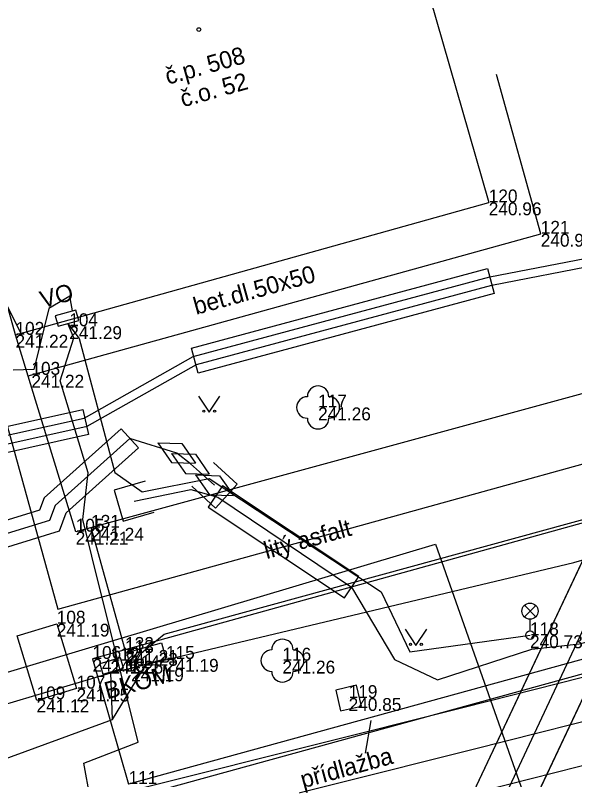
# Model space of a CAD drawing. Extents: x -599432 to -598680, y -1159407 to -1158632.
# Drawn here: x -599009.82 to -598996.8, y -1158877.11 to -1158859.33 of the extents above; entities that cross this region are included whole.
import ezdxf

# ---------------------------------------------------------------- set-up
doc = ezdxf.new("R2010")
doc.units = 0
for name, color, linetype in [('0004 VY - Body podrobné', 7, 'Continuous'), ('0005 VY - Body podrobné - čísla', 7, 'Continuous'), ('0006 VY - Body podrobné - výšky', 7, 'Continuous'), ('0007 ZA - Budova - zděná', 7, 'Continuous'), ('0010 ZA - Budova - označení', 7, 'Continuous'), ('0027 ZA - Silnice_cesta zpevněná', 7, 'Continuous'), ('0030 ZA - Chodník', 7, 'Continuous'), ('0031 ZA - Ostatní rozhraní', 7, 'Continuous'), ('0032 TE - Popis povrchu', 7, 'Continuous'), ('0034 ZA - Kultury - značky', 7, 'Continuous'), ('0035 ZA - Strom - značka', 7, 'Continuous'), ('0049 TE - Orientační _ popisná čísla', 7, 'Continuous'), ('0057 ZA - Doprava - BKOM buňky', 7, 'Continuous'), ('0058 TE - Doprava - BKOM popis', 7, 'Continuous'), ('0105 ZA - TSB - VO - buňky', 7, 'Continuous'), ('0106 TE - TSB - VO - popis', 7, 'Continuous'), ('0116 PV - budova převzatá z mapy', 7, 'Continuous'), ('0203 PV - BVK - kanalizace - dešťová přípojka', 7, 'Continuous'), ('0302 PV - RWE - NTL', 7, 'Continuous'), ('0308 PV - RWE - ochranné pásmo', 7, 'Continuous'), ('0352 PV - EON - NN', 7, 'Continuous'), ('0354 PV - EON - VN', 7, 'Continuous'), ('0367 PV - EON - VN chránička', 7, 'Continuous'), ('0407 PV - TSB - kabelové vedení přibližný zákres', 7, 'Continuous'), ('0455 PV - O2 - kabel nezaměřený', 7, 'Continuous'), ('0456 PV - O2 - sítě s NN', 7, 'Continuous'), ('0457 PV - O2 - kabelovod', 7, 'Continuous'), ('0551 PV - NETBOX - buňky', 7, 'Continuous'), ('0552 PV - NETBOX - vedení', 7, 'Continuous'), ('0552 PV - OT VUT', 7, 'Continuous'), ('0553 PV - NETBOX - chranička', 7, 'Continuous'), ('0652 PV - BKOM - kabely bez rozlišení', 7, 'Continuous'), ('0750 ZA - nerozlišené sítě - buňky', 7, 'Continuous')]:
    doc.layers.add(name, color=color, linetype=linetype)

msp = doc.modelspace()

# ---------------------------------------------------------------- linework, layer by layer
at = {"layer": '0004 VY - Body podrobné'}
for p, q in [((-598998.8, -1158863.68), (-598998.8, -1158863.68)), ((-598997.59, -1158864.41), (-598997.59, -1158864.41)), ((-599008.56, -1158866.56), (-599008.56, -1158866.56)), ((-599009.81, -1158866.76), (-599009.81, -1158866.76)), ((-599009.44, -1158867.69), (-599009.44, -1158867.69)), ((-599002.77, -1158868.45), (-599002.77, -1158868.45)), ((-599008.41, -1158871.34), (-599008.41, -1158871.34)), ((-599008.05, -1158871.25), (-599008.05, -1158871.25)), ((-599008.85, -1158873.48), (-599008.85, -1158873.48)), ((-598997.84, -1158873.75), (-598997.84, -1158873.75)), ((-599007.26, -1158874.09), (-599007.26, -1158874.09)), ((-599007.26, -1158874.16), (-599007.26, -1158874.16)), ((-599008.02, -1158874.3), (-599008.02, -1158874.3)), ((-599007.6, -1158874.34), (-599007.6, -1158874.34)), ((-599006.31, -1158874.3), (-599006.31, -1158874.3)), ((-599003.6, -1158874.34), (-599003.6, -1158874.34)), ((-599007.12, -1158874.52), (-599007.12, -1158874.52)), ((-599008.39, -1158874.99), (-599008.39, -1158874.99)), ((-599009.32, -1158875.24), (-599009.32, -1158875.24)), ((-599002.06, -1158875.21), (-599002.06, -1158875.21))]:
    msp.add_line(p, q, dxfattribs=at)
at = {"layer": '0007 ZA - Budova - zděná'}
msp.add_line((-599009.81, -1158866.76), (-598998.8, -1158863.68), dxfattribs=at)
at = {"layer": '0010 ZA - Budova - označení'}
msp.add_circle((-599005.545, -1158859.66), 0.0438, dxfattribs=at)
at = {"layer": '0027 ZA - Silnice_cesta zpevněná'}
msp.add_line((-598977.96, -1158869.18), (-599007.18, -1158877.21), dxfattribs=at)
at = {"layer": '0030 ZA - Chodník'}
for p, q in [((-598978.46, -1158863.18), (-599008.41, -1158871.34)), ((-598977.38, -1158865.8), (-599008.02, -1158874.3)), ((-599008.41, -1158871.34), (-599009.81, -1158866.76)), ((-599008.02, -1158874.3), (-599007.18, -1158877.21))]:
    msp.add_line(p, q, dxfattribs=at)
at = {"layer": '0031 ZA - Ostatní rozhraní'}
for p, q in [((-598997.59, -1158864.41), (-598998.616, -1158860.704)), ((-599009.519, -1158867.712), (-598997.59, -1158864.41)), ((-598977.872, -1158869.501), (-599007.092, -1158877.531)), ((-599007.26, -1158874.089), (-599008.052, -1158871.242))]:
    msp.add_line(p, q, dxfattribs=at)
at = {"layer": '0032 TE - Popis povrchu'}
msp.add_line((-599001.664, -1158876.492), (-599001.535, -1158875.734), dxfattribs=at)
at = {"layer": '0034 ZA - Kultury - značky'}
for points in [[(-599005.553, -1158868.187), (-599005.303, -1158868.562), (-599005.053, -1158868.187)], [(-599000.744, -1158873.61), (-599000.494, -1158873.985), (-599000.244, -1158873.61)]]:
    msp.add_lwpolyline(points, dxfattribs=at)
for centre in [(-599005.428, -1158868.537), (-599005.178, -1158868.537), (-599000.619, -1158873.96), (-599000.369, -1158873.96)]:
    msp.add_circle(centre, 0.025, dxfattribs=at)
at = {"layer": '0035 ZA - Strom - značka'}
for centre in [(-599002.77, -1158868.45), (-599003.6, -1158874.34)]:
    msp.add_circle(centre, 0.00025, dxfattribs=at)
for centre, start, end in [((-599002.77, -1158868.2), 0, 180), ((-599003.02, -1158868.45), 90, 270), ((-599002.52, -1158868.45), 270, 90), ((-599002.77, -1158868.7), 180, 360), ((-599003.6, -1158874.09), 0, 180), ((-599003.85, -1158874.34), 90, 270), ((-599003.35, -1158874.34), 270, 90), ((-599003.6, -1158874.59), 180, 360)]:
    msp.add_arc(centre, 0.25, start, end, dxfattribs=at)
at = {"layer": '0057 ZA - Doprava - BKOM buňky'}
for points in [[(-599006.31, -1158874.3), (-599007.12, -1158874.52), (-599007.221, -1158874.149), (-599006.411, -1158873.929)], [(-599007.781, -1158874.651), (-599007.3, -1158874.515), (-599007.368, -1158874.274), (-599007.849, -1158874.411)]]:
    msp.add_lwpolyline(points, close=True, dxfattribs=at)
at = {"layer": '0105 ZA - TSB - VO - buňky'}
for p, q in [((-598997.972, -1158873.319), (-598997.708, -1158873.055)), ((-598997.704, -1158873.318), (-598997.968, -1158873.053)), ((-598997.84, -1158873.65), (-598997.84, -1158873.375))]:
    msp.add_line(p, q, dxfattribs=at)
msp.add_lwpolyline([(-599008.819, -1158866.56), (-599008.336, -1158866.427), (-599008.403, -1158866.186), (-599008.885, -1158866.319)], close=True, dxfattribs=at)
for centre, radius in [((-598997.84, -1158873.188), 0.188), ((-598997.84, -1158873.75), 0.1)]:
    msp.add_circle(centre, radius, dxfattribs=at)
at = {"layer": '0116 PV - budova převzatá z mapy'}
for p, q in [((-599009.81, -1158866.76), (-599014.86, -1158848.7)), ((-599002.26, -1158851.67), (-598998.8, -1158863.68))]:
    msp.add_line(p, q, dxfattribs=at)
at = {"layer": '0203 PV - BVK - kanalizace - dešťová přípojka'}
msp.add_line((-599009.663, -1158866.757), (-599015.455, -1158855.336), dxfattribs=at)
msp.add_line((-599009.663, -1158866.757), (-599015.455, -1158855.336), dxfattribs=at)
at = {"layer": '0302 PV - RWE - NTL'}
msp.add_lwpolyline([(-599031.044, -1158884.383), (-598999.16, -1158876.4), (-598995.29, -1158875.42), (-598995.15, -1158875.39), (-598995.04, -1158875.36)], dxfattribs=at)
at = {"layer": '0308 PV - RWE - ochranné pásmo'}
msp.add_lwpolyline([(-599031.689, -1158883.514), (-599031.287, -1158883.413), (-598999.404, -1158875.43), (-598995.518, -1158874.446), (-598995.387, -1158874.418), (-598995.303, -1158874.395), (-598994.903, -1158874.286), (-598994.184, -1158874.697), (-598994.075, -1158875.097), (-598993.966, -1158875.497), (-598994.377, -1158876.216), (-598994.777, -1158876.325), (-598994.913, -1158876.362), (-598995.062, -1158876.394), (-598998.916, -1158877.37), (-599030.801, -1158885.353), (-599031.203, -1158885.454), (-599031.913, -1158885.028), (-599032.014, -1158884.626), (-599032.115, -1158884.224)], close=True, dxfattribs=at)
at = {"layer": '0352 PV - EON - NN'}
msp.add_lwpolyline([(-599021.682, -1158826.616), (-599018.026, -1158839.848), (-599017.168, -1158839.601), (-599017.124, -1158839.718), (-599017.057, -1158839.985), (-599017.919, -1158840.233), (-599016.234, -1158846.334), (-599013.125, -1158857.581), (-599012.296, -1158857.347), (-599012.256, -1158857.465), (-599012.187, -1158857.732), (-599013.017, -1158857.966), (-599008.822, -1158873.141), (-598963.861, -1158860.708)], dxfattribs=at)
at = {"layer": '0354 PV - EON - VN'}
for points in [[(-599068.426, -1158889.707), (-599062.435, -1158887.486), (-599057.559, -1158885.602), (-599053.514, -1158882.536), (-599048.468, -1158879.787), (-599040.575, -1158877.583), (-599039.069, -1158877.224), (-599035.277, -1158875.867), (-599021.599, -1158869.995), (-599019.639, -1158870.482), (-599018.747, -1158870.641), (-599017.491, -1158870.75), (-599015.995, -1158870.391), (-599015.549, -1158870.322), (-599008.216, -1158868.696), (-599005.678, -1158867.267), (-598998.773, -1158865.413), (-598996.328, -1158864.935), (-598994.319, -1158863.656), (-598989.416, -1158862.609), (-598988.122, -1158862.719), (-598986.867, -1158862.571), (-598978.725, -1158860.643), (-598971.459, -1158858.594)], [(-599068.354, -1158889.893), (-599062.365, -1158887.674), (-599057.461, -1158885.778), (-599053.406, -1158882.704), (-599048.392, -1158879.973), (-599040.525, -1158877.777), (-599039.011, -1158877.416), (-599035.203, -1158876.053), (-599021.581, -1158870.205), (-599019.681, -1158870.678), (-599018.773, -1158870.839), (-599017.509, -1158870.95), (-599015.965, -1158870.589), (-599015.511, -1158870.518), (-599008.144, -1158868.884), (-599005.602, -1158867.453), (-598998.727, -1158865.607), (-598996.252, -1158865.125), (-598994.241, -1158863.844), (-598989.404, -1158862.811), (-598988.118, -1158862.921), (-598986.833, -1158862.769), (-598978.675, -1158860.837), (-598971.401, -1158858.786)]]:
    msp.add_lwpolyline(points, dxfattribs=at)
at = {"layer": '0367 PV - EON - VN chránička'}
for p, q in [((-599005.718, -1158867.07), (-598998.828, -1158865.22)), ((-598998.828, -1158865.22), (-598998.672, -1158865.8)), ((-598998.672, -1158865.8), (-599005.562, -1158867.65)), ((-599005.562, -1158867.65), (-599005.718, -1158867.07)), ((-599015.595, -1158870.127), (-599008.245, -1158868.497)), ((-599008.245, -1158868.497), (-599008.115, -1158869.083)), ((-599008.115, -1158869.083), (-599015.465, -1158870.713))]:
    msp.add_line(p, q, dxfattribs=at)
at = {"layer": '0407 PV - TSB - kabelové vedení přibližný zákres'}
for p, q in [((-599008.545, -1158865.86), (-599009.036, -1158866.147)), ((-599008.484, -1158866.205), (-599008.545, -1158865.86)), ((-599009.036, -1158866.147), (-599009.384, -1158867.567)), ((-599008.452, -1158866.833), (-599008.593, -1158866.498)), ((-599008.593, -1158866.498), (-599008.325, -1158866.846)), ((-599008.771, -1158867.828), (-599008.452, -1158866.833)), ((-599008.325, -1158866.846), (-599007.502, -1158869.965)), ((-599009.384, -1158867.567), (-599009.862, -1158867.58)), ((-599008.121, -1158869.972), (-599008.771, -1158867.828)), ((-599008.243, -1158871.058), (-599008.121, -1158869.972)), ((-599007.502, -1158869.965), (-599006.864, -1158870.412)), ((-599006.864, -1158870.412), (-599005.307, -1158870.106)), ((-599005.307, -1158870.106), (-599002.705, -1158871.815)), ((-599008.031, -1158871.911), (-599008.243, -1158871.058)), ((-599002.705, -1158871.815), (-599001.301, -1158872.738)), ((-599006.96, -1158876.236), (-599008.031, -1158871.911)), ((-599001.301, -1158872.738), (-599000.638, -1158874.137)), ((-599000.638, -1158874.137), (-598997.84, -1158873.75)), ((-599008.223, -1158876.721), (-599006.96, -1158876.236)), ((-599006.22, -1158887.349), (-599008.223, -1158876.721))]:
    msp.add_line(p, q, dxfattribs=at)
at = {"layer": '0455 PV - O2 - kabel nezaměřený'}
for points in [[(-599011.61, -1158875.82), (-599007.59, -1158874.62), (-598996.82, -1158872.06), (-598955.03, -1158859.99), (-598940.58, -1158856.31), (-598931.77, -1158853.97)], [(-599004.95, -1158891.42), (-598992.56, -1158865)]]:
    msp.add_lwpolyline(points, dxfattribs=at)
at = {"layer": '0456 PV - O2 - sítě s NN'}
msp.add_lwpolyline([(-599004.95, -1158891.42), (-598992.56, -1158865)], dxfattribs=at)
at = {"layer": '0457 PV - O2 - kabelovod'}
for points in [[(-598994.01, -1158866.5), (-599005.01, -1158889.8)], [(-598992.66, -1158866.84), (-599003.78, -1158890.39)]]:
    msp.add_lwpolyline(points, dxfattribs=at)
at = {"layer": '0551 PV - NETBOX - buňky'}
for points in [[(-599006.499, -1158869.271), (-599005.943, -1158869.287)], [(-599006.499, -1158869.271), (-599006.177, -1158869.733)], [(-599005.943, -1158869.287), (-599005.621, -1158869.749)], [(-599006.179, -1158869.521), (-599005.623, -1158869.537)], [(-599006.179, -1158869.521), (-599005.857, -1158869.983)], [(-599005.623, -1158869.537), (-599005.301, -1158869.999)], [(-599006.177, -1158869.733), (-599005.621, -1158869.749)], [(-599005.71, -1158870.284), (-599005.156, -1158870.79), (-599004.65, -1158870.236), (-599005.204, -1158869.73)], [(-599005.857, -1158869.983), (-599005.301, -1158869.999)], [(-599005.619, -1158870.021), (-599005.063, -1158870.037)], [(-599005.619, -1158870.021), (-599005.297, -1158870.483)], [(-599005.063, -1158870.037), (-599004.741, -1158870.499)], [(-599006.796, -1158870.164), (-599007.515, -1158870.376), (-599007.304, -1158871.095), (-599006.584, -1158870.884)], [(-599005.297, -1158870.483), (-599004.741, -1158870.499)]]:
    msp.add_lwpolyline(points, dxfattribs=at)
at = {"layer": '0552 PV - NETBOX - vedení'}
for points in [[(-599007.05, -1158870.63), (-599005.73, -1158870.36), (-599005.1, -1158870.54), (-599001.99, -1158872.63), (-599000.99, -1158874.31), (-598999.99, -1158874.79), (-598997.8, -1158874.07), (-598996.7, -1158873.95), (-598994.84, -1158873.5), (-598993.019, -1158872.79), (-598991.84, -1158872.01), (-598990.22, -1158871.96), (-598984.72, -1158870.68), (-598978.84, -1158868.55), (-598975.909, -1158867.89)], [(-599006.06, -1158869.51), (-599006.06, -1158869.51), (-599007.15, -1158869.17), (-599007.15, -1158869.17), (-599008.89, -1158870.73), (-599009.02, -1158871.08), (-599010.62, -1158871.57), (-599015.34, -1158873.36), (-599021.01, -1158874.99), (-599029.72, -1158877.35), (-599032.35, -1158878.18), (-599038.52, -1158879.88), (-599044.56, -1158881.49), (-599050.4, -1158884.03), (-599052.74, -1158885.29), (-599055.15, -1158886.37), (-599057.94, -1158887.57), (-599060.68, -1158888.43), (-599062.55, -1158889.31)], [(-599005.74, -1158869.76), (-599005.74, -1158869.76), (-599006.06, -1158869.51)], [(-599005.18, -1158870.26), (-599005.18, -1158870.26), (-599005.74, -1158869.76)]]:
    msp.add_lwpolyline(points, dxfattribs=at)
at = {"layer": '0552 PV - OT VUT'}
msp.add_lwpolyline([(-599033.74, -1158881.244), (-599014.077, -1158875.825), (-599000.042, -1158871.632), (-598993.234, -1158890.936), (-598991.532, -1158891.542)], dxfattribs=at)
at = {"layer": '0553 PV - NETBOX - chranička'}
for points in [[(-599007.35, -1158868.947), (-599009.145, -1158870.556), (-599009.25, -1158870.837), (-599010.717, -1158871.286), (-599015.435, -1158873.075), (-599021.091, -1158874.701)], [(-599020.929, -1158875.279), (-599015.245, -1158873.645), (-599010.523, -1158871.854), (-599008.79, -1158871.323), (-599008.635, -1158870.904), (-599006.95, -1158869.393), (-599007.35, -1158868.947)]]:
    msp.add_lwpolyline(points, dxfattribs=at)
msp.add_lwpolyline([(-599004.994, -1158870.27), (-599005.326, -1158870.77), (-599002.156, -1158872.88), (-599001.824, -1158872.38)], close=True, dxfattribs=at)
at = {"layer": '0652 PV - BKOM - kabely bez rozlišení'}
for p, q in [((-599005.013, -1158889.795), (-598993.885, -1158866.227)), ((-599003.777, -1158890.385), (-598992.662, -1158866.844)), ((-599007.55, -1158875.71), (-599006.793, -1158874.464))]:
    msp.add_line(p, q, dxfattribs=at)
for points in [[(-599012.374, -1158857.616), (-599013.19, -1158857.86), (-599018.08, -1158859.1), (-599018.5, -1158859.81), (-599016.73, -1158866.41), (-599019.7, -1158871.25), (-599019.95, -1158872.38), (-599019.48, -1158873.04), (-599018.91, -1158874.17), (-599016.73, -1158875.93), (-599015.62, -1158876.75), (-599013.57, -1158877.37), (-599011.16, -1158877.03), (-599007.55, -1158875.71), (-599007.594, -1158874.617)], [(-599006.875, -1158874.155), (-599006.35, -1158873.72), (-598996.27, -1158870.96), (-598992.51, -1158869.87), (-598991.79, -1158872.08), (-598991.71, -1158872.5)], [(-599069.54, -1158906.27), (-599056.01, -1158902.46), (-599042.94, -1158898.82), (-599036.88, -1158897.21), (-599035.9, -1158896.65), (-599035.19, -1158895.15), (-599033.43, -1158892.94), (-599032.55, -1158892.85), (-599032.38, -1158891.47), (-599031.43, -1158887.7), (-599033.39, -1158880.98), (-599034.34, -1158877.53), (-599034.11, -1158876.42), (-599020.38, -1158872.59), (-599019.95, -1158872.38), (-599019.48, -1158873.04), (-599018.91, -1158874.17), (-599016.73, -1158875.93), (-599015.62, -1158876.75), (-599013.57, -1158877.37), (-599011.16, -1158877.03), (-599007.55, -1158875.71), (-599006.793, -1158874.464)]]:
    msp.add_lwpolyline(points, dxfattribs=at)
at = {"layer": '0750 ZA - nerozlišené sítě - buňky'}
for p, q in [((-599001.873, -1158874.91), (-599002.36, -1158875.023)), ((-599002.36, -1158875.023), (-599002.247, -1158875.51)), ((-599001.76, -1158875.397), (-599001.873, -1158874.91)), ((-599002.247, -1158875.51), (-599001.76, -1158875.397))]:
    msp.add_line(p, q, dxfattribs=at)
msp.add_lwpolyline([(-599008.85, -1158873.48), (-599008.39, -1158874.99), (-599009.311, -1158875.27), (-599009.771, -1158873.76)], close=True, dxfattribs=at)

# ---------------------------------------------------------------- texts
at = {"layer": '0005 VY - Body podrobné - čísla'}
for s, p in [('120', (-598998.8, -1158863.68)), ('121', (-598997.59, -1158864.41)), ('104', (-599008.56, -1158866.56)), ('102', (-599009.81, -1158866.76)), ('103', (-599009.44, -1158867.69)), ('117', (-599002.77, -1158868.45)), ('131', (-599008.05, -1158871.25)), ('105', (-599008.41, -1158871.34)), ('108', (-599008.85, -1158873.48)), ('118', (-598997.84, -1158873.75)), ('132', (-599007.26, -1158874.09)), ('106', (-599008.02, -1158874.3)), ('113', (-599007.26, -1158874.16)), ('115', (-599006.31, -1158874.3)), ('112', (-599007.6, -1158874.34)), ('116', (-599003.6, -1158874.34)), ('114', (-599007.12, -1158874.52)), ('107', (-599008.39, -1158874.99)), ('109', (-599009.32, -1158875.24)), ('119', (-599002.06, -1158875.21)), ('111', (-599007.18, -1158877.21))]:
    msp.add_text(s, height=0.3, dxfattribs=at).set_placement(p)
at = {"layer": '0006 VY - Body podrobné - výšky'}
for s, p in [('240.96', (-598998.8, -1158863.98)), ('240.98', (-598997.59, -1158864.71)), ('241.29', (-599008.56, -1158866.86)), ('241.22', (-599009.81, -1158867.06)), ('241.22', (-599009.44, -1158867.99)), ('241.26', (-599002.77, -1158868.75)), ('241.21', (-599008.41, -1158871.64)), ('241.24', (-599008.05, -1158871.55)), ('241.19', (-599008.85, -1158873.78)), ('240.73', (-598997.84, -1158874.05)), ('241.21', (-599007.26, -1158874.39)), ('241.23', (-599007.26, -1158874.46)), ('241.18', (-599008.02, -1158874.6)), ('241.26', (-599007.6, -1158874.64)), ('241.19', (-599006.31, -1158874.6)), ('241.26', (-599003.6, -1158874.64)), ('241.19', (-599007.12, -1158874.82)), ('241.15', (-599008.39, -1158875.29)), ('241.12', (-599009.32, -1158875.54)), ('240.85', (-599002.06, -1158875.51))]:
    msp.add_text(s, height=0.3, dxfattribs=at).set_placement(p)
at = {"layer": '0032 TE - Popis povrchu'}
for s, rotation, p in [('bet.dl.50x50', 15.4717, (-599005.608, -1158866.297)), ('litý asfalt', 15.5048, (-599003.969, -1158871.979)), ('přídlažba', 15.3662, (-599003.119, -1158877.311))]:
    msp.add_text(s, height=0.4, rotation=rotation, dxfattribs=at).set_placement(p)
at = {"layer": '0049 TE - Orientační _ popisná čísla'}
for s, p in [('č.p. 508', (-599006.267, -1158860.945)), ('č.o. 52', (-599005.915, -1158861.469))]:
    msp.add_text(s, height=0.4, rotation=15.6438, dxfattribs=at).set_placement(p)
at = {"layer": '0058 TE - Doprava - BKOM popis'}
msp.add_text('BKOM', height=0.4, rotation=15.5048, dxfattribs=at).set_placement((-599007.676, -1158875.242))
at = {"layer": '0106 TE - TSB - VO - popis'}
msp.add_text('VO', height=0.4, rotation=15.6287, dxfattribs=at).set_placement((-599009.173, -1158866.147))

doc.saveas('drawing.dxf')
